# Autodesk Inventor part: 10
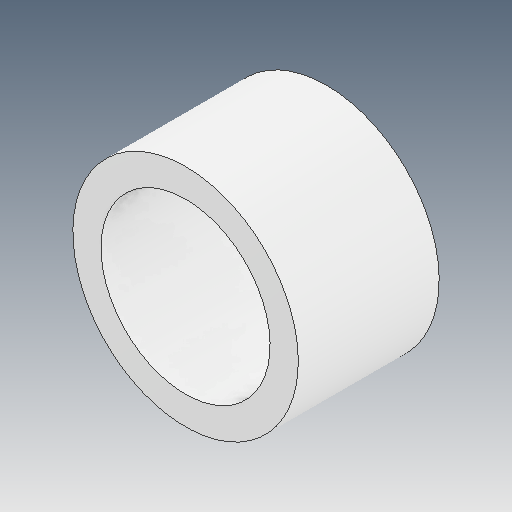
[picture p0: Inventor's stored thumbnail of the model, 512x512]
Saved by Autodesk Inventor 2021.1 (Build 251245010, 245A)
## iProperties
Created: 2021-06
Part Number: 10
Material: Ogólny
Document SubType Name: Modeling
Designer: user
Density: 1 g/cm^3
Appearance: Domyślna
Author: user
Revision Number: ÈÎºÎ
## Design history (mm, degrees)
feature "ÊäÈë1"
node "Bryła1"
